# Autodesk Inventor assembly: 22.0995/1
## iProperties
Created: 2012-04
Part Number: 22.0995/1
Document SubType Name: Assembly
Designer: Administrator
Description: END CAP 45-45 DEG GRAY
Vendor: S
Stock Number: 22.0995_1 END CAP 45-45 DEG GRAY
Author: Administrator
